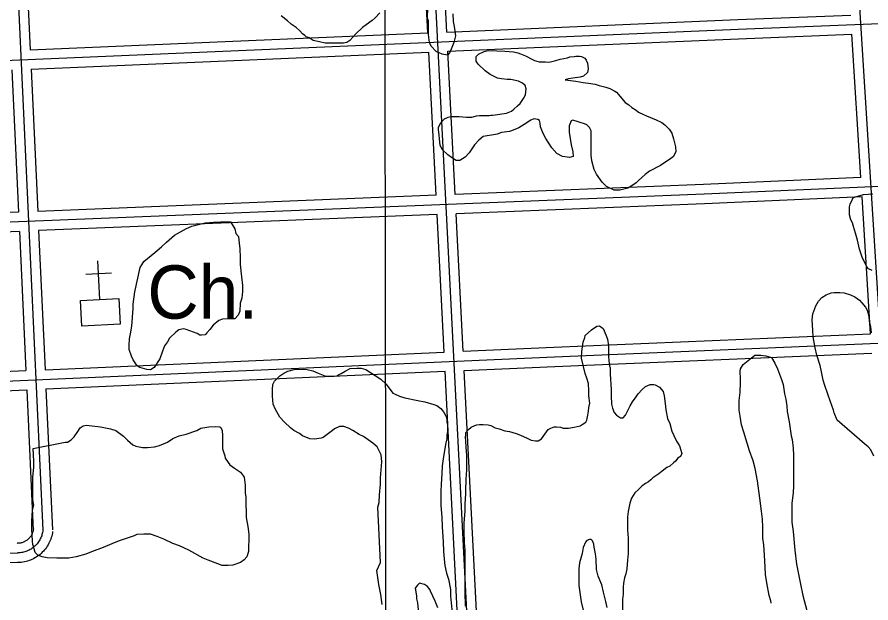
# Model space of a CAD drawing. Extents: x 3313442 to 3351311, y 721974 to 747360.
# Drawn here: x 3332744 to 3334074, y 731274 to 732187 of the extents above; entities that cross this region are included whole.
import ezdxf

# ---------------------------------------------------------------- set-up
doc = ezdxf.new("R2010")
doc.units = 0
for name, color, linetype in [('V-BLDG-OTLN', 7, 'Continuous'), ('V-GRID-MAJR', 7, 'Continuous'), ('V-ROAD-CNTR', 7, 'Continuous'), ('V-SITE-OTLN', 7, 'Continuous'), ('V-SITE-OTLN-IDEN', 7, 'Continuous'), ('V-SITE-VEGE', 7, 'Continuous')]:
    doc.layers.add(name, color=color, linetype=linetype)

msp = doc.modelspace()

# ---------------------------------------------------------------- linework, layer by layer
at = {"layer": 'V-BLDG-OTLN'}
msp.add_lwpolyline([(3332842.6, 731745.7), (3332902.1, 731748.9), (3332904.2, 731708.9), (3332844.7, 731705.7)], close=True, dxfattribs=at)
at = {"layer": 'V-GRID-MAJR'}
msp.add_spline([(3333324.1, 727373.9), (3333315.3, 733432.2), (3333306.5, 739494), (3333297.7, 745555.7), (3333297.7, 745559.2)], degree=3, dxfattribs=at)
at = {"layer": 'V-ROAD-CNTR'}
for points in [[(3332694.5, 733302), (3332784.1, 731387.8)], [(3334144.9, 730789.2), (3334026.9, 732674.1)], [(3333449.6, 731159.9), (3333373.7, 732645.2)], [(3333413.3, 732163.7), (3333388.7, 732646)], [(3333383.3, 732162.4), (3333372.2, 732380.2)], [(3332753.7, 732357), (3332764.1, 732136)], [(3330854.8, 732040), (3331531.5, 732068.3), (3333867, 732168.1), (3335281.8, 732225.3)], [(3333413.3, 732163.7), (3333866.4, 732183.1), (3334042.1, 732190.2)], [(3332764.1, 732136), (3333383.3, 732162.4)], [(3333414.8, 732133.8), (3333867.6, 732153.1), (3334044, 732160.2)], [(3334058, 731937), (3334044, 732160.2)], [(3332765.5, 732106), (3333384.9, 732132.5)], [(3333396.3, 731909.4), (3333384.9, 732132.5)], [(3333426.3, 731910.7), (3333414.8, 732133.8)], [(3332735.5, 732104.7), (3332745.9, 731883.1)], [(3332765.5, 732106), (3332775.9, 731884.3)], [(3335327.4, 731977.3), (3333813.7, 731911.3), (3331665.1, 731824.3), (3330985.5, 731786.5)], [(3334058, 731937), (3333813, 731926.3), (3333426.3, 731910.7)], [(3333396.3, 731909.4), (3332775.9, 731884.3)], [(3334059.9, 731907), (3333814.3, 731896.3), (3333427.8, 731880.7)], [(3334073.2, 731693.6), (3334059.9, 731907)], [(3332745.9, 731883.1), (3332003.3, 731853.1)], [(3333397.8, 731879.5), (3332777.3, 731854.4)], [(3333408.8, 731665.3), (3333397.8, 731879.5)], [(3333438.7, 731666.7), (3333427.8, 731880.7)], [(3332747.3, 731853.1), (3332004.6, 731823.1)], [(3332747.3, 731853.1), (3332757.5, 731636.4)], [(3332777.3, 731854.4), (3332787.4, 731637.7)], [(3331111.5, 731542.3), (3331168, 731556), (3331552.8, 731567.9), (3333580.6, 731657.9), (3335191.6, 731725.6)], [(3333438.7, 731666.7), (3333579.9, 731672.9), (3334073.2, 731693.6)], [(3332787.4, 731637.7), (3333408.8, 731665.3)], [(3333440.3, 731636.7), (3333581.2, 731642.9), (3334075.1, 731663.7)], [(3332014.4, 731603.4), (3332757.5, 731636.4)], [(3332788.8, 731607.8), (3333410.3, 731635.4)], [(3333434.6, 731159.1), (3333410.3, 731635.4)], [(3333464.6, 731160.6), (3333440.3, 731636.7)], [(3331115, 731527.7), (3331170, 731541), (3331553.4, 731552.9), (3332758.9, 731606.4)], [(3332758.9, 731606.4), (3332769.1, 731387.1)], [(3332788.8, 731607.8), (3332799.1, 731388.5)], [(3332769.3, 731389.9), (3332769.1, 731388.5), (3332768.9, 731387.4), (3332768.6, 731386.3), (3332768.3, 731385.2), (3332767.9, 731384.1), (3332767.5, 731383), (3332767.1, 731382), (3332766.6, 731381), (3332766.1, 731380), (3332765.5, 731379), (3332764.8, 731378.1), (3332764.2, 731377.2), (3332763.5, 731376.3), (3332762.7, 731375.5), (3332761.9, 731374.6), (3332761.1, 731373.9), (3332760.3, 731373.1), (3332759.4, 731372.4), (3332758.5, 731371.8), (3332757.5, 731371.1), (3332756.6, 731370.6), (3332755.6, 731370), (3332754.6, 731369.5), (3332753.5, 731369.1), (3332752.5, 731368.7), (3332751.4, 731368.3), (3332750.3, 731368), (3332749.2, 731367.8), (3332748.1, 731367.6), (3332747, 731367.4), (3332745.9, 731367.3), (3332744.6, 731367.3), (3332744, 731367.2)], [(3332784.1, 731387.8), (3332783.9, 731386), (3332783.5, 731384.2), (3332783.1, 731382.5), (3332782.6, 731380.8), (3332782.1, 731379.1), (3332781.4, 731377.4), (3332780.7, 731375.7), (3332779.9, 731374.1), (3332779.1, 731372.5), (3332778.1, 731371), (3332777.2, 731369.5), (3332776.1, 731368.1), (3332775, 731366.7), (3332773.8, 731365.3), (3332772.5, 731364), (3332771.2, 731362.8), (3332769.9, 731361.6), (3332768.5, 731360.5), (3332767, 731359.4), (3332765.5, 731358.4), (3332764, 731357.5), (3332762.4, 731356.7), (3332760.8, 731355.9), (3332759.1, 731355.2), (3332757.4, 731354.5), (3332755.7, 731354), (3332754, 731353.5), (3332752.3, 731353.1), (3332750.5, 731352.8), (3332748.7, 731352.5), (3332746.9, 731352.3), (3332745.1, 731352.3), (3332744.2, 731352.2)], [(3332799, 731385.7), (3332798.7, 731383.6), (3332798.2, 731381.1), (3332797.7, 731378.7), (3332797, 731376.4), (3332796.2, 731374), (3332795.3, 731371.7), (3332794.3, 731369.5), (3332793.3, 731367.3), (3332792.1, 731365.1), (3332790.8, 731363), (3332789.5, 731360.9), (3332788, 731358.9), (3332786.5, 731357), (3332784.8, 731355.2), (3332783.1, 731353.4), (3332781.3, 731351.7), (3332779.5, 731350.1), (3332777.6, 731348.5), (3332775.6, 731347.1), (3332773.5, 731345.7), (3332771.4, 731344.5), (3332769.2, 731343.3), (3332767, 731342.2), (3332764.7, 731341.3), (3332762.4, 731340.4), (3332760.1, 731339.6), (3332757.7, 731339), (3332755.3, 731338.4), (3332752.9, 731338), (3332750.4, 731337.6), (3332748, 731337.4), (3332745.6, 731337.3), (3332744.4, 731337.2)], [(3332744.2, 731352.2), (3331239, 731295.1)], [(3332744.7, 731337.3), (3331239.5, 731280.1)]]:
    msp.add_lwpolyline(points, dxfattribs=at)
at = {"layer": 'V-SITE-OTLN'}
for p, q in [((3332872.9, 731747.3), (3332869.7, 731807.2)), ((3332890.7, 731788.3), (3332850.8, 731786.2))]:
    msp.add_line(p, q, dxfattribs=at)
at = {"layer": 'V-SITE-VEGE'}
for points in [[(3333309, 732193.9), (3333301.7, 732186), (3333296.8, 732181.7), (3333287.7, 732175.1), (3333281.6, 732170.8), (3333271.3, 732161.1), (3333262.1, 732150.8), (3333257.3, 732147.7), (3333252.4, 732146.5), (3333223.8, 732146.5), (3333214.7, 732148.4), (3333204.9, 732150.8), (3333198.9, 732154.5), (3333194, 732156.3), (3333192.2, 732158.1), (3333188.5, 732161.2), (3333184.3, 732165.5), (3333178.2, 732170.9), (3333170.9, 732175.8), (3333164.8, 732181.3), (3333155.1, 732189.2)], [(3333422.2, 732191.9), (3333422.8, 732180.4), (3333424.6, 732172.5), (3333426.4, 732157.9), (3333423.9, 732147.5), (3333417.8, 732131.7), (3333414.2, 732127.5), (3333405.7, 732129.3), (3333396.6, 732133.6), (3333388.7, 732141.5), (3333386.2, 732147.6), (3333384.4, 732159.7), (3333384.4, 732181), (3333383.2, 732185.3), (3333383.3, 732201.7)], [(3333530.9, 732084.2), (3333524.5, 732087.3), (3333513, 732089.6), (3333507, 732090), (3333498.2, 732090.7), (3333491.9, 732092), (3333480.8, 732097.8), (3333472.7, 732103.5), (3333461.9, 732113.6), (3333458.6, 732118.6), (3333458.9, 732125.4), (3333462.6, 732129.1), (3333471.4, 732133.4), (3333477.4, 732134.8), (3333491.2, 732134.7), (3333503.3, 732134.1), (3333517.1, 732133), (3333523.5, 732131.3), (3333527.9, 732130), (3333535.6, 732126.6), (3333546.4, 732120.9), (3333549.4, 732119.5), (3333556.8, 732117.5), (3333562.5, 732117.2), (3333566.9, 732117.2), (3333571.3, 732116.8), (3333574.6, 732117.2), (3333578.7, 732118.2), (3333582.7, 732119.5), (3333589.5, 732121.5), (3333601.2, 732123.8), (3333604.9, 732124.9), (3333611.3, 732125.5), (3333614, 732126.2), (3333619.7, 732126.2), (3333623.1, 732125.5), (3333627.8, 732122.8), (3333630.2, 732120.1), (3333632.2, 732115.1), (3333633.2, 732106.3), (3333632.2, 732100.9), (3333625.8, 732095.2), (3333620.7, 732093.2), (3333609.6, 732091.9), (3333602.5, 732090.9), (3333597.5, 732089.5), (3333614, 732087.2), (3333625.7, 732085.1), (3333633.5, 732084.1), (3333643.9, 732082.4), (3333650.6, 732080.4), (3333660.7, 732078), (3333666.8, 732075.7), (3333674.9, 732071.9), (3333677.2, 732069.9), (3333691, 732054.1), (3333696.7, 732050.1), (3333701.4, 732046), (3333707.8, 732042), (3333711.8, 732038.9), (3333719.6, 732035.2), (3333724.3, 732033.2)], [(3333724.3, 732033.2), (3333733, 732029.8), (3333739.1, 732027.1), (3333747.8, 732022.7), (3333752.8, 732019), (3333759.6, 732012.6), (3333763.3, 732006.2), (3333766.3, 731997.5), (3333769, 731985), (3333769.6, 731977.6), (3333766.2, 731969.9), (3333762.2, 731966.5), (3333746, 731956.1), (3333728.9, 731947.1), (3333721.8, 731942), (3333711.4, 731932.3), (3333708, 731928.9), (3333702.9, 731925.2), (3333695.2, 731920.5), (3333682.7, 731917.5), (3333673.7, 731917.2), (3333661.6, 731922.9), (3333654.8, 731929.7), (3333646.1, 731942.1), (3333642.4, 731949.5), (3333638.7, 731963), (3333637.7, 731972.1), (3333637.8, 731993.3), (3333638.1, 732002.3), (3333637.8, 732010.1), (3333635.4, 732014.8), (3333631.1, 732019.2), (3333627.7, 732020.5), (3333621, 732022.6), (3333616.3, 732024.2), (3333609.5, 732026.3), (3333606.8, 732025.3), (3333603.8, 732017.5), (3333603.5, 732007.8), (3333606.8, 731988.3), (3333609.1, 731977.1), (3333610.1, 731969.7), (3333604.4, 731968.1), (3333593, 731969.8), (3333584.2, 731974.8), (3333576.8, 731983.6), (3333567.4, 731997.7), (3333563.1, 732005.8), (3333559, 732016.2), (3333558.7, 732021.6), (3333557.4, 732026), (3333555, 732027.3), (3333548.6, 732028.4), (3333543.9, 732026.7), (3333533.5, 732019.6), (3333525.4, 732014.6), (3333514, 732009.6), (3333510.6, 732008.9), (3333498.1, 732007.2), (3333491.7, 732004.9), (3333488.7, 732003.9), (3333469.9, 732000.9), (3333463.1, 731995.5), (3333456.4, 731987.8), (3333448, 731975.7), (3333441.6, 731968.9), (3333433.2, 731963.6), (3333427.8, 731963.6), (3333420.4, 731968.3), (3333414.7, 731972.3), (3333405.9, 731980.8), (3333402.6, 731987.5), (3333401.6, 731997.6), (3333401.2, 732003.6), (3333399.9, 732011.4), (3333399.9, 732015.1), (3333402.3, 732019.8), (3333407, 732026.2), (3333409.7, 732028.5), (3333415.1, 732030.9), (3333419.4, 732032.2), (3333432.2, 732032.2), (3333443.7, 732031.2), (3333452.1, 732031.2), (3333454.1, 732031.5), (3333459.5, 732033.2), (3333464.2, 732033.5), (3333479.3, 732033.5), (3333481.7, 732034.2), (3333484, 732034.2), (3333488.4, 732034.8), (3333505.9, 732037.2), (3333513.7, 732040.5), (3333517.7, 732043.5), (3333523.4, 732048.6), (3333527.5, 732052.6), (3333532.5, 732060), (3333535.6, 732065.7), (3333536.9, 732075.5), (3333534.9, 732080.5), (3333530.9, 732084.2)], [(3334075.7, 731792.1), (3334069.6, 731795.1), (3334067.2, 731798.1), (3334059.9, 731812.8), (3334056.9, 731822.5), (3334055.7, 731825.5), (3334052.6, 731839.5), (3334049.6, 731850.5), (3334046.6, 731860.8), (3334044.8, 731866.3), (3334042.3, 731871.2), (3334040.5, 731879.1), (3334040.5, 731891.3), (3334041.1, 731895.5), (3334044.8, 731903.4), (3334046.6, 731905.9), (3334053.3, 731908.3), (3334061.8, 731910.7), (3334076.4, 731911.9)], [(3334078.2, 731502.9), (3334073.5, 731513), (3334069.2, 731517.7), (3334063.5, 731522.4), (3334020.8, 731559.1), (3334016.4, 731570.6), (3334015.1, 731574.9), (3334010, 731589.4), (3334006.7, 731599.8), (3334001.7, 731613), (3333999.3, 731621.4), (3333996.6, 731634.2), (3333994.3, 731644.3), (3333989.6, 731660.4), (3333986.6, 731671.9), (3333983.9, 731689), (3333982.9, 731699.5), (3333982.3, 731715.6), (3333983.3, 731725), (3333988, 731737.1), (3333992.1, 731744.5), (3333997.1, 731750.3), (3334003.9, 731754.3), (3334011.9, 731757.6), (3334016.6, 731758), (3334025.4, 731758), (3334032.1, 731757.6), (3334041.9, 731754.6), (3334048.3, 731751.2), (3334055.7, 731746.1), (3334059.7, 731741.8), (3334065.4, 731735), (3334067.7, 731730.3), (3334070.1, 731721.2), (3334071.1, 731713.5), (3334072.8, 731704.7), (3334073.8, 731695)], [(3333442.4, 731269.6), (3333441.8, 731291.5), (3333441.9, 731356.6), (3333440.6, 731368.2), (3333440.1, 731387), (3333440.1, 731399.2), (3333441.9, 731417.5), (3333441.9, 731428.4), (3333442.6, 731444.2), (3333442.6, 731449.1), (3333443.2, 731467.3), (3333444.4, 731481.9), (3333444.5, 731504.4), (3333443.3, 731516.6), (3333442.7, 731527.6), (3333442.1, 731531.8), (3333442.7, 731537.3), (3333442.7, 731539.7), (3333446.9, 731544.6), (3333451.2, 731548.2), (3333456.7, 731550.7), (3333459.7, 731551.9), (3333464, 731552.5), (3333469.5, 731552.5), (3333477.4, 731551.9), (3333481.6, 731550.6), (3333488.3, 731547), (3333494.4, 731545.8), (3333503.5, 731542.7), (3333510.8, 731541.5), (3333521.2, 731538.4), (3333527.9, 731536), (3333538.2, 731531.1), (3333544.3, 731528.1), (3333551, 731526.8), (3333555.2, 731526.8), (3333560.7, 731529.9), (3333571.1, 731544.4), (3333575.3, 731546.9), (3333580.2, 731548.7), (3333583.8, 731548.7), (3333589.9, 731548.1), (3333594.2, 731546.9), (3333602.7, 731546.8), (3333611.2, 731548.1), (3333620.9, 731550.5), (3333624, 731552.3), (3333629.5, 731555.9), (3333631.3, 731559), (3333632.5, 731566.9), (3333633.8, 731573), (3333634.4, 731579), (3333635.6, 731585.7), (3333634.4, 731597.3), (3333634.4, 731604.6), (3333633.8, 731616.2), (3333631.4, 731624.7), (3333628.3, 731632), (3333622.9, 731655.7), (3333623.5, 731666.1), (3333625.4, 731680.7), (3333627.8, 731688), (3333628.4, 731691), (3333638.2, 731700.1), (3333646.7, 731705.6), (3333650.9, 731706.2), (3333656.4, 731701.9), (3333660.7, 731692.2), (3333663.1, 731685.5), (3333664.9, 731675.1), (3333664.9, 731658.1), (3333665.5, 731652), (3333666.7, 731643.5), (3333667.3, 731641.1), (3333667.3, 731630.7)], [(3333918.1, 731273.9), (3333917.5, 731277.6), (3333915.1, 731286.1), (3333911.5, 731305.6), (3333909.6, 731318.9), (3333909.1, 731330.5), (3333907.9, 731348.8), (3333906.7, 731365.2), (3333905.5, 731375.5), (3333905.5, 731392.6), (3333904.9, 731404.7), (3333903.1, 731417.5), (3333900.7, 731437.6), (3333897, 731464.4), (3333893.4, 731483.8), (3333890.4, 731496), (3333884.3, 731511.2), (3333880.7, 731523.4), (3333875.8, 731540.4), (3333872.2, 731552), (3333869.8, 731565.4), (3333868.6, 731574.5), (3333868.6, 731589.7), (3333869.8, 731602.5), (3333870.5, 731618.3), (3333870.5, 731623.2), (3333869.9, 731635.3), (3333870.5, 731639), (3333874.8, 731645.7), (3333885.1, 731654.2), (3333893, 731660.3), (3333902.2, 731660.2), (3333910.1, 731659.6), (3333918.6, 731656.6), (3333924, 731648.1), (3333928.3, 731638.9), (3333934.3, 731622.5), (3333936.8, 731614.6), (3333939.2, 731600), (3333941, 731592.1), (3333942.8, 731581.1), (3333943.4, 731572.6), (3333946.4, 731556.8), (3333947.6, 731545.8), (3333949.5, 731534.9), (3333950.7, 731528.8), (3333952.5, 731515.4), (3333953.1, 731504.4), (3333953, 731457), (3333952.4, 731446), (3333950.5, 731429.6), (3333950.5, 731400.4), (3333952.3, 731385.8), (3333955.3, 731356.6), (3333957.7, 731334.7), (3333963.8, 731303.7), (3333967.4, 731286), (3333977.7, 731247.1)], [(3333309.8, 731337.3), (3333305.7, 731423.7), (3333307.5, 731431), (3333308.1, 731442.6), (3333310, 731459.6), (3333310, 731469.3), (3333311.8, 731494.3), (3333310.6, 731505.2), (3333304.6, 731517.4), (3333297.9, 731523.5), (3333283.3, 731533.8), (3333276.6, 731536.9), (3333266.9, 731543), (3333260.2, 731546.6), (3333252.9, 731549.1), (3333246.2, 731549.1), (3333238.3, 731545.5), (3333235.2, 731543), (3333220.6, 731532.1), (3333217.6, 731530.9), (3333207.2, 731529.7), (3333199.9, 731530.3), (3333188.4, 731534.6), (3333183.5, 731538.2), (3333175, 731543.1), (3333169.5, 731547.4), (3333160.4, 731555.9), (3333153.1, 731563.8), (3333146.4, 731576), (3333142.8, 731583.9), (3333141.6, 731596.7), (3333141.6, 731607), (3333142.2, 731614.9), (3333144.7, 731619.8), (3333153.2, 731628.3), (3333159.3, 731632.5), (3333165.4, 731635.6), (3333175.1, 731638), (3333189.7, 731638.6), (3333195.8, 731638), (3333204.3, 731636.1), (3333212.8, 731632.5), (3333223.2, 731628.2), (3333228, 731627.6), (3333237.8, 731627.6), (3333242, 731628.2), (3333244.5, 731630), (3333248.7, 731631.8), (3333254.8, 731635.5), (3333262.7, 731639.7), (3333273.1, 731640.3), (3333279.8, 731640.3), (3333287.1, 731637.9), (3333292.5, 731634.2), (3333310.2, 731623.2), (3333318.7, 731615.3), (3333329, 731601.3), (3333331.4, 731600.1), (3333339.3, 731596.4), (3333347.8, 731594), (3333367.9, 731589.7), (3333378.9, 731587.9), (3333392.9, 731583.6), (3333397.7, 731581.8), (3333403.8, 731577.5), (3333408, 731572), (3333412.3, 731564.7)], [(3333667.3, 731630.7), (3333669.1, 731607), (3333669.1, 731597.3), (3333669.7, 731583.9), (3333670.9, 731577.8), (3333673.9, 731571.1), (3333677.5, 731566.8), (3333683.6, 731562.6), (3333687.9, 731562.6), (3333691.5, 731566.8), (3333698.9, 731581.4), (3333702.5, 731587.5), (3333708, 731595.4), (3333711, 731600.2), (3333717.1, 731606.9), (3333722.6, 731611.8), (3333729.9, 731614.8), (3333735.4, 731614.8), (3333737.8, 731614.2), (3333744.5, 731610.6), (3333750, 731603.9), (3333751.8, 731597.2), (3333753, 731585), (3333754.2, 731575.3), (3333756.6, 731561.9), (3333760.3, 731554), (3333763.3, 731541.8), (3333766.9, 731535.1), (3333770.6, 731526.6), (3333773, 731523.5), (3333775.4, 731519.3), (3333779.1, 731507.1), (3333777.2, 731502.8), (3333774.8, 731501.6), (3333773, 731499.8), (3333769.3, 731495.5), (3333766.3, 731492.5), (3333760.2, 731487.6), (3333755.9, 731485.2), (3333748.6, 731479.7), (3333743.1, 731475.5), (3333734, 731469.4), (3333731, 731466.4), (3333727.3, 731463.3), (3333722.4, 731460.3), (3333717, 731456.1), (3333710.9, 731450.6), (3333706, 731445.7), (3333700.5, 731437.8), (3333698.1, 731429.9), (3333695.6, 731417.1), (3333694.4, 731408.6), (3333694.4, 731387.9), (3333695.6, 731375.2)], [(3333412.3, 731564.7), (3333412.9, 731561.1), (3333412.9, 731556.8), (3333414.1, 731551.3), (3333414.1, 731542.2), (3333412.9, 731535.5), (3333412.9, 731530), (3333411.6, 731524), (3333408, 731502.7), (3333406.1, 731488.1), (3333405.5, 731475.9), (3333404.3, 731458.9), (3333403.6, 731448.5), (3333403.6, 731426), (3333405.4, 731407.8), (3333406, 731393.2), (3333407.2, 731369.4), (3333407.8, 731354.8), (3333409.6, 731337.2), (3333410.2, 731332.9), (3333412.6, 731320.8), (3333415.6, 731311.6), (3333418.7, 731295.2), (3333418.7, 731284.9), (3333419.9, 731274.5), (3333421.7, 731253.8)], [(3333662.6, 731267.5), (3333660.8, 731276.7), (3333657.1, 731291.3), (3333654.7, 731302.8), (3333648.7, 731316.2), (3333646.2, 731326.6), (3333645.6, 731342.4), (3333644.4, 731350.9), (3333642.6, 731361.2), (3333642, 731366.1), (3333640.2, 731371), (3333637.8, 731373.4), (3333635.3, 731373.4), (3333631.1, 731371.6), (3333629.2, 731369.2), (3333625.6, 731360.7), (3333623.8, 731351.5), (3333619.5, 731336.9), (3333618.9, 731327.8), (3333618.8, 731301.7), (3333620.6, 731287), (3333622.4, 731276.1), (3333626.7, 731259.1)], [(3333695.6, 731375.2), (3333695.5, 731351.4), (3333694.3, 731341.1), (3333693.7, 731327.7), (3333691.9, 731319.8), (3333690, 731313.7), (3333688.2, 731305.2), (3333687.6, 731299.1), (3333687.6, 731288.2), (3333686.9, 731279.7), (3333686.9, 731228)], [(3333312.2, 731272.2), (3333310.4, 731287.4), (3333307.3, 731303.2), (3333304.3, 731325.1), (3333309.8, 731337.3)], [(3333399.2, 731266.6), (3333394.9, 731277), (3333387.6, 731292.8), (3333386.4, 731295.2), (3333382.8, 731300.1), (3333378.5, 731303.2), (3333370.6, 731305), (3333367.6, 731302), (3333363.9, 731297.7), (3333365.7, 731285.5), (3333365.7, 731280.7), (3333367.5, 731274.6), (3333369.9, 731247.8)]]:
    msp.add_lwpolyline(points, dxfattribs=at)
for points in [[(3332927, 731758.8), (3332935.6, 731797.1), (3332938.1, 731801.3), (3332941.1, 731806.2), (3332958.1, 731820.2), (3332968.5, 731829.3), (3332976.4, 731836.6), (3332989.2, 731847.5), (3332998.3, 731852.4), (3333007.5, 731857.8), (3333016, 731861.5), (3333028.2, 731864.5), (3333036.7, 731866.3), (3333049.5, 731867.5), (3333060.4, 731868.1), (3333076.2, 731868.1), (3333082.9, 731857.1), (3333084.7, 731849.8), (3333088.4, 731845), (3333089.6, 731834.6), (3333090.8, 731826.7), (3333091.4, 731812.1), (3333091.4, 731801.8), (3333093.2, 731782.3), (3333095, 731768.9), (3333095, 731759.8), (3333093.7, 731749.4), (3333091.3, 731741.5), (3333090.7, 731728.8), (3333088.2, 731722.7), (3333082.7, 731717.2), (3333072.4, 731717.2), (3333063.9, 731716.6), (3333057.8, 731714.2), (3333049.3, 731706.9), (3333043.8, 731700.2), (3333039.5, 731695.4), (3333036.5, 731692.3), (3333031, 731691.7), (3333028.6, 731691.7), (3333024.3, 731694.2), (3333007.3, 731700.3), (3333003, 731701.5), (3332995.7, 731699.7), (3332990.9, 731696), (3332981.1, 731686.9), (3332978.1, 731681.4), (3332973.2, 731674.8), (3332970.1, 731666.8), (3332965.9, 731654.7), (3332957.3, 731641.3), (3332951.8, 731637.7), (3332945.8, 731638.3), (3332934.8, 731641.3), (3332930.6, 731643.8), (3332924.5, 731652.9), (3332922.1, 731659), (3332918.4, 731669.3), (3332918.4, 731675.4), (3332919.1, 731685.8), (3332920.3, 731693.7), (3332922.7, 731705.8), (3332924.6, 731733.2), (3332924.6, 731739.9)], [(3332768.6, 731515), (3332818.5, 731524.7), (3332822.1, 731524.7), (3332828.2, 731528.3), (3332832.5, 731533.2), (3332838.6, 731541.7), (3332842.2, 731547.2), (3332846.5, 731550.2), (3332852, 731551.4), (3332873.9, 731548.9), (3332889.1, 731545.9), (3332897.6, 731542.8), (3332909.7, 731534.3), (3332915.8, 731528.2), (3332924.3, 731520.9), (3332928.6, 731518.5), (3332938.9, 731516.6), (3332946.8, 731516.6), (3332957.8, 731517.8), (3332965.7, 731519.6), (3332977.9, 731525.1), (3332986.4, 731530.6), (3332996.1, 731534.8), (3333007.1, 731537.2), (3333023.5, 731543.3), (3333030.2, 731546.9), (3333042.4, 731548.7), (3333052.7, 731549.3), (3333059.4, 731548.7), (3333061.2, 731547.5), (3333063.1, 731543.2), (3333063.7, 731535.3), (3333063.6, 731514.6), (3333067.3, 731503.7), (3333067.9, 731500), (3333072.7, 731493.3), (3333075.2, 731489.7), (3333082.5, 731484.2), (3333091.6, 731478.1), (3333096.4, 731472), (3333097.7, 731470.2), (3333098.9, 731458), (3333098.8, 731445.9), (3333100, 731439.2), (3333100, 731425.2), (3333100.6, 731418.5), (3333100.6, 731407.5), (3333103, 731393.5), (3333104.8, 731381.4), (3333104.8, 731374.1), (3333104.2, 731360.7), (3333104.2, 731354.6), (3333101.8, 731346.1), (3333097.5, 731341.8), (3333092, 731337.6), (3333079.8, 731333.3), (3333072.5, 731332.7), (3333063.4, 731332.7), (3333056.7, 731335.2), (3333041.5, 731341.3), (3333033.6, 731344.3), (3333011.1, 731356.5), (3332996.5, 731363.2), (3332986.2, 731366.9), (3332972.2, 731373.6), (3332961.9, 731377.9), (3332951.5, 731381.5), (3332941.2, 731381.6), (3332930.2, 731381), (3332926, 731379.1), (3332913.8, 731374.9), (3332902.9, 731371.3), (3332891.3, 731366.4), (3332877.9, 731360.9), (3332859.6, 731354.3), (3332851.1, 731350.6), (3332835.9, 731346.4), (3332824.3, 731344), (3332805.5, 731344), (3332790.9, 731344.6), (3332783, 731346.5), (3332776.3, 731348.9), (3332772, 731353.2), (3332770.2, 731358.6), (3332768.4, 731365.3), (3332767.8, 731370.8), (3332766.6, 731389.7), (3332766.6, 731402.5), (3332767.9, 731418.3), (3332769.7, 731426.8), (3332768.5, 731435.3), (3332768.5, 731470.6), (3332769.8, 731485.2), (3332769.8, 731495.5)]]:
    msp.add_lwpolyline(points, close=True, dxfattribs=at)

# ---------------------------------------------------------------- texts
at = {"layer": 'V-SITE-OTLN-IDEN'}
msp.add_text('Ch.', height=83, dxfattribs=at).set_placement((3332946.6, 731717.3))

doc.saveas('drawing.dxf')
